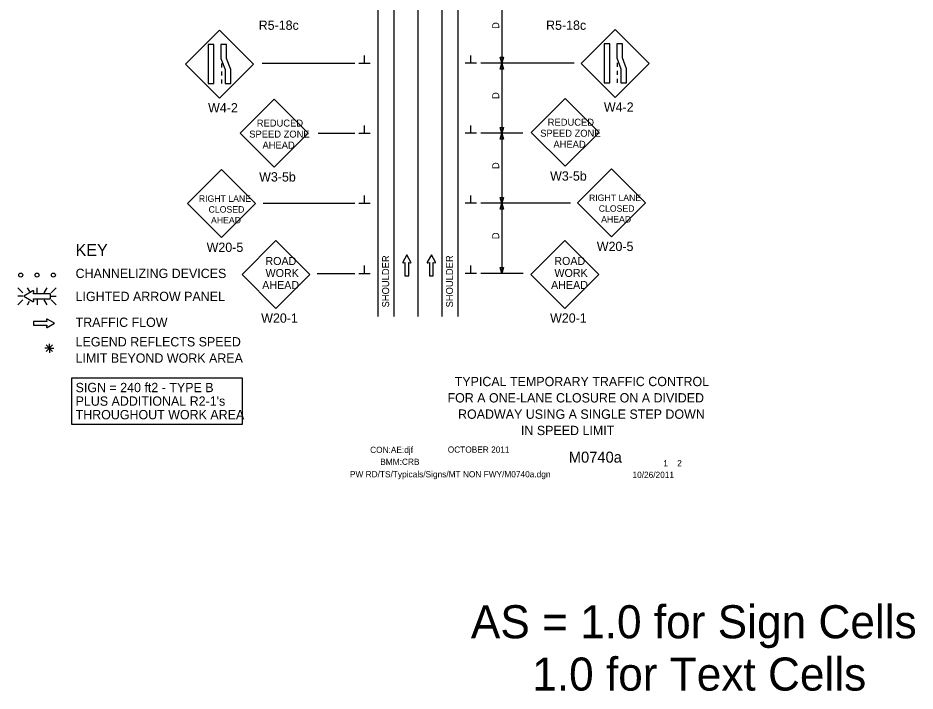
# Model space of a CAD drawing. Extents: x 16739 to 18475, y 5720 to 6924.
# Drawn here: x 16739 to 17635, y 5720 to 6393 of the extents above; entities that cross this region are included whole.
import ezdxf

# ---------------------------------------------------------------- set-up
doc = ezdxf.new("R2010")
doc.units = 0
for name, color, linetype in [('ALI_LEGAL_EX', 7, 'Continuous'), ('BORDER', 7, 'Continuous'), ('BORDER_SIGNAL_WO', 7, 'Continuous'), ('MT_SCRATCH_LEVEL_E', 7, 'Continuous'), ('PAVT_EDGE_EX', 7, 'Continuous'), ('TRAFFIC_SIGNS_PR', 7, 'Continuous'), ('TYPICAL_TEXT_DIMEN_EX', 7, 'Continuous'), ('TYPICAL_TEXT_DIMEN_PR', 7, 'Continuous')]:
    doc.layers.add(name, color=color, linetype=linetype)

msp = doc.modelspace()

# ---------------------------------------------------------------- linework, layer by layer
at = {"layer": 'ALI_LEGAL_EX'}
msp.add_line((17138.25, 6923.7), (17138.25, 6094.51), dxfattribs=at)
for points in [[(17138.25, 6323.7), (17138.25, 6298.7)], [(17138.25, 6223.7), (17138.25, 6198.7)], [(17138.25, 6123.7), (17138.25, 6098.7)]]:
    msp.add_lwpolyline(points, dxfattribs=at)
at = {"layer": 'MT_SCRATCH_LEVEL_E'}
for p, q in [((17127.36, 6155.9), (17123.25, 6148.66)), ((17127.36, 6155.9), (17123.25, 6148.66)), ((17131.51, 6148.66), (17127.36, 6155.9)), ((17131.51, 6148.66), (17127.36, 6155.9)), ((17151.92, 6155.9), (17147.81, 6148.66)), ((17151.92, 6155.9), (17147.81, 6148.66)), ((17156.07, 6148.66), (17151.92, 6155.9)), ((17156.07, 6148.66), (17151.92, 6155.9)), ((17123.73, 6147.98), (17125.51, 6148.29)), ((17123.73, 6147.98), (17125.51, 6148.29)), ((17125.51, 6148.29), (17125.51, 6135.03)), ((17125.51, 6148.29), (17125.51, 6135.03)), ((17129.25, 6135.03), (17129.25, 6148.29)), ((17129.25, 6148.29), (17131.03, 6147.98)), ((17129.25, 6135.03), (17129.25, 6148.29)), ((17129.25, 6148.29), (17131.03, 6147.98)), ((17148.29, 6147.98), (17150.07, 6148.29)), ((17148.29, 6147.98), (17150.07, 6148.29)), ((17150.07, 6148.29), (17150.07, 6135.03)), ((17150.07, 6148.29), (17150.07, 6135.03)), ((17153.81, 6135.03), (17153.81, 6148.29)), ((17153.81, 6148.29), (17155.59, 6147.98)), ((17153.81, 6135.03), (17153.81, 6148.29)), ((17153.81, 6148.29), (17155.59, 6147.98)), ((17125.51, 6135.03), (17129.25, 6135.03)), ((17125.51, 6135.03), (17129.25, 6135.03)), ((17150.07, 6135.03), (17153.81, 6135.03)), ((17150.07, 6135.03), (17153.81, 6135.03)), ((16767.45, 6089.53), (16754.19, 6089.53)), ((16754.19, 6089.53), (16754.19, 6085.79)), ((16767.45, 6089.53), (16754.19, 6089.53)), ((16754.19, 6089.53), (16754.19, 6085.79)), ((16767.14, 6091.31), (16767.45, 6089.53)), ((16767.14, 6091.31), (16767.45, 6089.53)), ((16775.06, 6087.68), (16767.82, 6091.79)), ((16775.06, 6087.68), (16767.82, 6091.79)), ((16754.19, 6085.79), (16767.45, 6085.79)), ((16754.19, 6085.79), (16767.45, 6085.79)), ((16767.45, 6085.79), (16767.14, 6084.02)), ((16767.45, 6085.79), (16767.14, 6084.02)), ((16767.82, 6083.54), (16775.06, 6087.68)), ((16767.82, 6083.54), (16775.06, 6087.68))]:
    msp.add_line(p, q, dxfattribs=at)
for centre, start, end in [((17123.66, 6148.43), 150.42484, 279.96381), ((17123.66, 6148.43), 150.42484, 279.96381), ((17131.1, 6148.44), 260.03619, 29.77312), ((17131.1, 6148.44), 260.03619, 29.77312), ((17148.22, 6148.43), 150.42484, 279.96381), ((17148.22, 6148.43), 150.42484, 279.96381), ((17155.66, 6148.44), 260.03619, 29.77312), ((17155.66, 6148.44), 260.03619, 29.77312), ((16767.6, 6091.39), 60.42484, 189.96381), ((16767.6, 6091.39), 60.42484, 189.96381), ((16767.6, 6083.95), 170.03619, 299.77312), ((16767.6, 6083.95), 170.03619, 299.77312)]:
    msp.add_arc(centre, 0.463, start, end, dxfattribs=at)
at = {"layer": 'PAVT_EDGE_EX'}
for p, q in [((17098.25, 6923.7), (17098.25, 6094.51)), ((17114.25, 6923.7), (17114.25, 6094.51)), ((17162.25, 6923.7), (17162.25, 6094.51)), ((17178.25, 6923.7), (17178.25, 6094.51))]:
    msp.add_line(p, q, dxfattribs=at)
at = {"layer": 'TRAFFIC_SIGNS_PR'}
for p, q in [((16940.01, 6380.43), (16906.06, 6346.49)), ((16973.95, 6346.49), (16940.01, 6380.43)), ((17335.64, 6381.13), (17301.7, 6347.19)), ((17369.58, 6347.19), (17335.64, 6381.13)), ((16906.06, 6346.49), (16940.01, 6312.55)), ((16940.01, 6312.55), (16973.95, 6346.49)), ((16942.06, 6347.1), (16942.06, 6343.1)), ((17301.7, 6347.19), (17335.64, 6313.25)), ((17335.64, 6313.25), (17369.58, 6347.19)), ((17337.69, 6347.8), (17337.69, 6343.8)), ((17337.69, 6339.8), (17337.69, 6335.8)), ((16942.06, 6339.1), (16942.06, 6335.1)), ((16942.06, 6331.1), (16942.06, 6327.1)), ((17337.69, 6331.8), (17337.69, 6327.8)), ((16994.81, 6311.42), (16960.86, 6277.48)), ((17028.75, 6277.48), (16994.81, 6311.42)), ((17285.62, 6312.28), (17251.68, 6278.34)), ((17319.56, 6278.34), (17285.62, 6312.28)), ((16960.86, 6277.48), (16994.81, 6243.53)), ((16994.81, 6243.53), (17028.75, 6277.48)), ((17251.68, 6278.34), (17285.62, 6244.4)), ((17285.62, 6244.4), (17319.56, 6278.34)), ((16942.05, 6241.09), (16908.11, 6207.15)), ((16975.99, 6207.15), (16942.05, 6241.09)), ((17332.03, 6241.95), (17298.09, 6208.01)), ((17365.97, 6208.01), (17332.03, 6241.95)), ((16908.11, 6207.15), (16942.05, 6173.2)), ((16942.05, 6173.2), (16975.99, 6207.15)), ((17298.09, 6208.01), (17332.03, 6174.07)), ((17332.03, 6174.07), (17365.97, 6208.01)), ((16996.58, 6170.34), (16962.64, 6136.4)), ((17030.52, 6136.4), (16996.58, 6170.34)), ((17285.33, 6170.41), (17251.39, 6136.47)), ((17319.27, 6136.47), (17285.33, 6170.41)), ((16962.64, 6136.4), (16996.58, 6102.46)), ((16996.58, 6102.46), (17030.52, 6136.4)), ((17251.39, 6136.47), (17285.33, 6102.53)), ((17285.33, 6102.53), (17319.27, 6136.47)), ((16738.65, 6123.11), (16743.58, 6118.18)), ((16750.41, 6119.29), (16748.2, 6123.11)), ((16757.73, 6118.18), (16757.73, 6123.11)), ((16764.96, 6118.18), (16767.81, 6123.11)), ((16771.88, 6118.18), (16776.81, 6123.12)), ((16743.58, 6114.62), (16738.65, 6114.62)), ((16738.65, 6106.14), (16743.58, 6111.07)), ((16748.16, 6106.13), (16750.27, 6109.8)), ((16757.73, 6111.07), (16757.73, 6106.13)), ((16767.86, 6106.13), (16765.01, 6111.07)), ((16771.88, 6114.62), (16776.81, 6114.62)), ((16771.88, 6111.07), (16776.81, 6106.13))]:
    msp.add_line(p, q, dxfattribs=at)
for points in [[(17324.52, 6366.86), (17324.52, 6327.8), (17330.13, 6327.8), (17330.13, 6366.86)], [(17337.19, 6366.86), (17337.19, 6352.88), (17341.37, 6341.78), (17341.37, 6327.8), (17346.99, 6327.8), (17346.99, 6341.78), (17342.81, 6352.88), (17342.81, 6366.86)], [(16928.89, 6366.16), (16928.89, 6327.1), (16934.5, 6327.1), (16934.5, 6366.16)], [(16941.56, 6366.16), (16941.56, 6352.18), (16945.74, 6341.08), (16945.74, 6327.1), (16951.35, 6327.1), (16951.35, 6341.08), (16947.17, 6352.18), (16947.17, 6366.16)]]:
    msp.add_lwpolyline(points, close=True, dxfattribs=at)
for points in [[(16753.66, 6119.9), (16744.37, 6114.62), (16753.66, 6109.3)], [(16754.53, 6109.93), (16754.13, 6112.2), (16771.14, 6112.2), (16771.14, 6117), (16754.13, 6117), (16754.53, 6119.28)]]:
    msp.add_lwpolyline(points, dxfattribs=at)
for centre in [(16741.44, 6135.74), (16757.74, 6135.74), (16774.04, 6135.74)]:
    msp.add_circle(centre, 2, dxfattribs=at)
for centre, radius, start, end in [((16753.94, 6119.38), 0.598, 350.73078, 118.89165), ((16753.94, 6109.83), 0.597, 241.48329, 9.95933)]:
    msp.add_arc(centre, radius, start, end, dxfattribs=at)
at = {"layer": 'TYPICAL_TEXT_DIMEN_EX'}
for p, q in [((16770.13, 6062.75), (16765.6, 6062.75)), ((16773.32, 6065.94), (16766.94, 6059.57)), ((16766.95, 6065.94), (16773.32, 6059.57)), ((16770.13, 6062.75), (16770.13, 6067.21)), ((16770.13, 6062.75), (16773.32, 6062.75)), ((16770.13, 6062.75), (16774.61, 6062.75)), ((16770.13, 6062.75), (16770.13, 6058.25))]:
    msp.add_line(p, q, dxfattribs=at)
msp.add_lwpolyline([(16792.55, 6033.03), (16962.92, 6033.03), (16962.92, 5986.47), (16792.55, 5986.47)], close=True, dxfattribs=at)
at = {"layer": 'TYPICAL_TEXT_DIMEN_PR'}
for p, q in [((17222.25, 6417.44), (17222.25, 6347.44)), ((17085.12, 6347.44), (17085.12, 6355.22)), ((17191.38, 6347.44), (17191.38, 6355.22)), ((17222.25, 6347.44), (17220.68, 6353.3)), ((17220.68, 6353.3), (17222.25, 6353.3)), ((17222.25, 6347.44), (17220.68, 6353.3)), ((17220.68, 6353.3), (17222.25, 6353.3)), ((17222.25, 6353.3), (17223.82, 6353.3)), ((17223.82, 6353.3), (17222.25, 6347.44)), ((17222.25, 6353.3), (17223.82, 6353.3)), ((17223.82, 6353.3), (17222.25, 6347.44)), ((16982.71, 6347.44), (17075.25, 6347.44)), ((17079.5, 6347.44), (17090.75, 6347.44)), ((17197, 6347.44), (17185.75, 6347.44)), ((17294.49, 6347.44), (17201.25, 6347.44)), ((17220.68, 6341.57), (17222.25, 6347.44)), ((17222.25, 6341.57), (17220.68, 6341.57)), ((17222.25, 6347.44), (17222.25, 6277.44)), ((17222.25, 6347.44), (17223.82, 6341.57)), ((17223.82, 6341.57), (17222.25, 6341.57)), ((17038.76, 6277.44), (17075.25, 6277.44)), ((17079.5, 6277.44), (17090.75, 6277.44)), ((17085.12, 6277.44), (17085.12, 6285.22)), ((17197, 6277.44), (17185.75, 6277.44)), ((17191.38, 6277.44), (17191.38, 6285.22)), ((17243.39, 6277.44), (17201.25, 6277.44)), ((17222.25, 6277.44), (17220.68, 6283.3)), ((17220.68, 6283.3), (17222.25, 6283.3)), ((17220.68, 6271.57), (17222.25, 6277.44)), ((17220.68, 6271.57), (17222.25, 6277.44)), ((17222.25, 6283.3), (17223.82, 6283.3)), ((17223.82, 6283.3), (17222.25, 6277.44)), ((17222.25, 6277.44), (17222.25, 6207.44)), ((17222.25, 6277.44), (17223.82, 6271.57)), ((17222.25, 6277.44), (17223.82, 6271.57)), ((17222.25, 6271.57), (17220.68, 6271.57)), ((17222.25, 6271.57), (17220.68, 6271.57)), ((17223.82, 6271.57), (17222.25, 6271.57)), ((17223.82, 6271.57), (17222.25, 6271.57)), ((17085.12, 6207.44), (17085.12, 6215.22)), ((17191.38, 6207.44), (17191.38, 6215.22)), ((16983.86, 6207.44), (17075.25, 6207.44)), ((17079.5, 6207.44), (17090.75, 6207.44)), ((17197, 6207.44), (17185.75, 6207.44)), ((17291.05, 6207.44), (17201.25, 6207.44)), ((17222.25, 6207.44), (17220.68, 6213.3)), ((17220.68, 6213.3), (17222.25, 6213.3)), ((17222.25, 6207.44), (17220.68, 6213.3)), ((17220.68, 6213.3), (17222.25, 6213.3)), ((17220.68, 6201.57), (17222.25, 6207.44)), ((17222.25, 6213.3), (17223.82, 6213.3)), ((17223.82, 6213.3), (17222.25, 6207.44)), ((17222.25, 6213.3), (17223.82, 6213.3)), ((17223.82, 6213.3), (17222.25, 6207.44)), ((17222.25, 6207.44), (17222.25, 6137.44)), ((17222.25, 6207.44), (17223.82, 6201.57)), ((17222.25, 6201.57), (17220.68, 6201.57)), ((17223.82, 6201.57), (17222.25, 6201.57)), ((17085.12, 6137.44), (17085.12, 6145.22)), ((17191.38, 6137.44), (17191.38, 6145.22)), ((17222.25, 6137.44), (17220.68, 6143.3)), ((17220.68, 6143.3), (17222.25, 6143.3)), ((17222.25, 6143.3), (17223.82, 6143.3)), ((17223.82, 6143.3), (17222.25, 6137.44)), ((17037.69, 6137.44), (17075.25, 6137.44)), ((17079.5, 6137.44), (17090.75, 6137.44)), ((17197, 6137.44), (17185.75, 6137.44)), ((17243.52, 6137.44), (17201.25, 6137.44))]:
    msp.add_line(p, q, dxfattribs=at)

# ---------------------------------------------------------------- texts
at = {"layer": 'BORDER'}
for s, p in [('TYPICAL TEMPORARY TRAFFIC CONTROL', (17175.21, 6024.8)), ('FOR A ONE-LANE CLOSURE ON A DIVIDED', (17168.02, 6008.5)), ('ROADWAY USING A SINGLE STEP DOWN', (17178.54, 5992.2)), ('IN SPEED LIMIT', (17241.42, 5975.9))]:
    msp.add_text(s, height=9.3, dxfattribs=at).set_placement(p)
at = {"layer": 'BORDER_SIGNAL_WO'}
for s, height, p in [('CON:AE:djf', 6.2, (17090.69, 5958.06)), ('    OCTOBER 2011    ', 6.2, (17159.08, 5958.34)), ('    M0740a   ', 11, (17272.86, 5948.38)), ('BMM:CRB   ', 6.2, (17100.81, 5946.17)), (' 1    2 ', 6.2, (17381.45, 5944.7)), ('PW RD/TS/Typicals/Signs/MT NON FWY/M0740a.dgn    ', 6.2, (17070.55, 5933.71)), ('10/26/2011    ', 6.2, (17352.93, 5933.13)), ('AS = 1.0 for Sign Cells', 33.0301, (17191.35, 5772.93)), ('     1.0 for Text Cells', 33.0301, (17191.35, 5720.7))]:
    msp.add_text(s, height=height, dxfattribs=at).set_placement(p)
at = {"layer": 'TRAFFIC_SIGNS_PR'}
for s, height, p in [('R5-18c', 9.3, (16979.27, 6380.76)), ('R5-18c', 9.3, (17266.53, 6380.76)), ('W4-2', 9.3, (16928.7, 6298.25)), ('W4-2', 9.3, (17324.34, 6298.95)), ('REDUCED', 7, (16977.38, 6284.11)), ('REDUCED', 7, (17268.19, 6284.97)), ('SPEED ZONE', 7, (16969.87, 6273.11)), ('SPEED ZONE', 7, (17260.68, 6273.97)), ('AHEAD', 7, (16983.07, 6262.11)), ('AHEAD', 7, (17273.88, 6262.97)), ('W3-5b', 9.3, (16979.75, 6229.23)), ('W3-5b', 9.3, (17270.56, 6230.1)), ('RIGHT LANE', 6.5, (16919.45, 6208.89)), ('RIGHT LANE', 6.5, (17309.43, 6209.76)), ('CLOSED', 6.5, (17319.17, 6199.01)), ('CLOSED', 6.5, (16929.19, 6198.14)), ('AHEAD', 6.5, (16931.62, 6187.39)), ('AHEAD', 6.5, (17321.6, 6188.26)), ('W20-5', 9.3, (16927.26, 6158.9)), ('W20-5', 9.3, (17317.24, 6159.77)), ('ROAD', 8, (16986.01, 6145.82)), ('ROAD', 8, (17274.76, 6145.89)), ('WORK', 8, (16986.14, 6133.82)), ('WORK', 8, (17274.89, 6133.89)), ('AHEAD', 8, (16982.78, 6121.82)), ('AHEAD', 8, (17271.53, 6121.89)), ('W20-1', 9.3, (16981.79, 6088.16)), ('W20-1', 9.3, (17270.54, 6088.23))]:
    msp.add_text(s, height=height, dxfattribs=at).set_placement(p)
at = {"layer": 'TYPICAL_TEXT_DIMEN_EX'}
for s, height, p in [('KEY', 12, (16796.28, 6154.84)), ('CHANNELIZING DEVICES', 9.3, (16796.28, 6132.79)), ('LIGHTED ARROW PANEL', 9.3, (16796.28, 6109.8)), ('TRAFFIC FLOW', 9.3, (16796.28, 6084)), ('LEGEND REFLECTS SPEED', 9.3, (16796.28, 6064.49)), ('LIMIT BEYOND WORK AREA', 9.3, (16796.28, 6048.19)), ('SIGN = 240 ft2 - TYPE B', 9.3, (16796.28, 6018.79)), ("PLUS ADDITIONAL R2-1's", 9.3, (16796.28, 6005.24)), ('THROUGHOUT WORK AREA', 9.3, (16796.28, 5991.69))]:
    msp.add_text(s, height=height, dxfattribs=at).set_placement(p)
at = {"layer": 'TYPICAL_TEXT_DIMEN_PR'}
for s, p in [('D', (17219.69, 6381.66)), ('D', (17219.69, 6311.66)), ('D', (17219.69, 6241.66)), ('D', (17219.69, 6171.66)), ('SHOULDER', (17109.67, 6103.45)), ('SHOULDER', (17173.53, 6103.45))]:
    msp.add_text(s, height=7, rotation=90, dxfattribs=at).set_placement(p)

doc.saveas('drawing.dxf')
